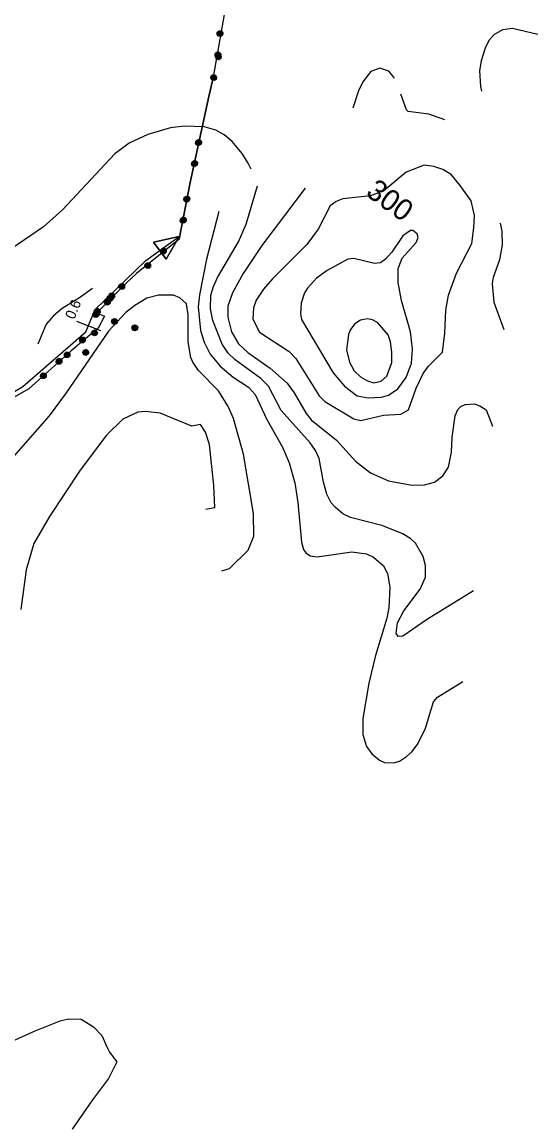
# Model space of a CAD drawing. Extents: x -645676 to -642474, y -1077513 to -1072613.
# Drawn here: x -643335 to -643033, y -1077131 to -1076485 of the extents above; entities that cross this region are included whole.
import ezdxf

# ---------------------------------------------------------------- set-up
doc = ezdxf.new("R2010")
doc.units = 0
for name, color, linetype in [('KULTURY_STAV', 7, 'Continuous'), ('OBVOD_PU', 7, 'Continuous'), ('PC_NAVRH', 7, 'Continuous'), ('PC_STAN_NAVRH', 7, 'Continuous'), ('SPRAV_HR_STAV', 7, 'Continuous'), ('VRSTEVNICE', 7, 'Continuous'), ('Vrstevnice_z_kladn_', 7, 'Continuous'), ('Vrstevnice_zd_razn_n____popis', 7, 'Continuous')]:
    doc.layers.add(name, color=color, linetype=linetype)

# ---------------------------------------------------------------- blocks, each defined once
blk = doc.blocks.new('$944')
blk.add_line((0, 1.5), (0, -1.5))
blk = doc.blocks.new('$920')
for points in [[(0, 0), (-2.8, 1.25), (-2.8, -1.25), (0, 0)], [(-2.8, 1.25), (0, 0), (-2.8, -1.25), (-2.8, 1.25)]]:
    blk.add_lwpolyline(points)
blk = doc.blocks.new('2$0620')
for points in [[(-1.07, 0.32), (-0.88, 0.13), (-0.88, -0.14), (-1.07, -0.33), (-1.34, -0.33), (-1.53, -0.14), (-1.53, 0.13), (-1.34, 0.32), (-1.07, 0.32), (-1.08, 0.28), (-1.32, 0.28), (-1.4, 0.2), (-1, 0.2), (-0.92, 0.12), (-1.48, 0.12), (-1.48, 0.04), (-0.92, 0.04), (-0.92, -0.04), (-1.48, -0.04), (-1.48, -0.12), (-0.92, -0.12), (-1, -0.2), (-1.4, -0.2), (-1.32, -0.28), (-1.08, -0.28)], [(1.43, 0.32), (1.62, 0.13), (1.62, -0.14), (1.43, -0.33), (1.16, -0.33), (0.97, -0.14), (0.97, 0.13), (1.16, 0.32), (1.43, 0.32), (1.4, 0.28), (1.16, 0.28), (1.08, 0.2), (1.48, 0.2), (1.56, 0.12), (1, 0.12), (1, 0.04), (1.56, 0.04), (1.56, -0.04), (1, -0.04), (1, -0.12), (1.56, -0.12), (1.48, -0.2), (1.08, -0.2), (1.16, -0.28), (1.4, -0.28)]]:
    blk.add_lwpolyline(points)

msp = doc.modelspace()

# ---------------------------------------------------------------- linework, layer by layer
at = {"layer": 'KULTURY_STAV'}
msp.add_lwpolyline([(-643217.03, -1076480.59), (-643223.78, -1076519.44), (-643226.07, -1076528.7), (-643236.93, -1076579.11), (-643243.33, -1076612.31), (-643268.3, -1076632.39), (-643274.14, -1076637.84), (-643275.51, -1076639.12), (-643291.65, -1076655.29), (-643287.15, -1076657.23), (-643290.93, -1076664.25), (-643306.74, -1076677.52), (-643331.48, -1076699.85), (-643347.3, -1076708.85)], dxfattribs=at)
at = {"layer": 'OBVOD_PU'}
msp.add_lwpolyline([(-643217.03, -1076480.59), (-643223.78, -1076519.44), (-643226.07, -1076528.7), (-643236.93, -1076579.11), (-643243.33, -1076612.31), (-643268.3, -1076632.39), (-643274.14, -1076637.84), (-643275.51, -1076639.12), (-643291.65, -1076655.29), (-643287.15, -1076657.23), (-643290.93, -1076664.25), (-643306.74, -1076677.52), (-643331.48, -1076699.85), (-643347.3, -1076708.85)], dxfattribs=at)
at = {"layer": 'PC_NAVRH'}
msp.add_lwpolyline([(-643797.12, -1076951.31), (-643789.53, -1076927.82), (-643783.02, -1076908.06), (-643774.79, -1076905.34), (-643762.9, -1076905.19), (-643748.59, -1076909.49), (-643740.43, -1076907.63), (-643712.08, -1076895.74), (-643647.09, -1076856.49), (-643620.93, -1076839.88), (-643580.45, -1076819.48), (-643516.12, -1076783.47), (-643467.4, -1076763.65), (-643449.91, -1076757.58), (-643363.17, -1076715.2), (-643334.98, -1076698.56), (-643297.97, -1076666.45), (-643292.62, -1076653.44), (-643262.84, -1076624.65), (-643243.46, -1076610.62)], dxfattribs=at)
at = {"layer": 'SPRAV_HR_STAV'}
for p, q in [((-643217.03, -1076480.59), (-643223.78, -1076519.44)), ((-643226.07, -1076528.7), (-643223.78, -1076519.44)), ((-643236.93, -1076579.11), (-643226.07, -1076528.7)), ((-643243.33, -1076612.31), (-643236.93, -1076579.11)), ((-643243.33, -1076612.31), (-643268.3, -1076632.39)), ((-643274.14, -1076637.84), (-643275.51, -1076639.12)), ((-643268.3, -1076632.39), (-643274.14, -1076637.84)), ((-643275.51, -1076639.12), (-643291.65, -1076655.29)), ((-643291.65, -1076655.29), (-643287.15, -1076657.23)), ((-643287.15, -1076657.23), (-643290.93, -1076664.25)), ((-643290.93, -1076664.25), (-643306.74, -1076677.52)), ((-643331.48, -1076699.85), (-643306.74, -1076677.52)), ((-643331.48, -1076699.85), (-643347.3, -1076708.85))]:
    msp.add_line(p, q, dxfattribs=at)
at = {"layer": 'VRSTEVNICE'}
for points in [[(-643033.11, -1076492.36), (-643048.05, -1076488.82), (-643053.85, -1076489.7), (-643058.98, -1076492.52), (-643061.96, -1076495.93), (-643063.95, -1076500.32), (-643066.31, -1076507.83), (-643067.39, -1076513.49), (-643066.81, -1076522.75), (-643066.21, -1076525.46)], [(-643117.14, -1076518.12), (-643117.57, -1076517.37), (-643120.47, -1076513.89), (-643125.68, -1076512.15), (-643131.04, -1076514.03), (-643135.82, -1076520.12), (-643138.28, -1076525.33), (-643141.5, -1076535.56)], [(-643087.59, -1076542.38), (-643097.01, -1076539.09), (-643109.17, -1076537.35), (-643110.18, -1076536.48), (-643113.55, -1076527.29)], [(-643201.27, -1076571.25), (-643202.87, -1076567.76), (-643206.49, -1076561.97), (-643212.28, -1076555.02), (-643217.06, -1076551.11), (-643221.84, -1076548.36), (-643228.79, -1076546.33), (-643240.38, -1076546.04), (-643248.49, -1076547.05), (-643261.81, -1076550.82), (-643272.67, -1076556.03), (-643281.07, -1076562.26), (-643311.78, -1076594.99), (-643322.93, -1076604.98), (-643341.46, -1076617.73)], [(-643070.87, -1076818.1), (-643097.87, -1076834.81), (-643112.36, -1076844.81), (-643114.96, -1076844.95), (-643116.27, -1076843.07), (-643115.4, -1076836.84), (-643111.65, -1076829.91), (-643102.22, -1076817.15), (-643099.03, -1076810.19), (-643099.03, -1076803.24), (-643100.34, -1076798.03), (-643104.97, -1076790.21), (-643107.58, -1076787.75), (-643112.36, -1076784.71), (-643124.52, -1076779.93), (-643143.06, -1076775.15), (-643147.4, -1076772.98), (-643152.04, -1076769.21), (-643154.21, -1076766.6), (-643156.82, -1076761.53), (-643158.84, -1076754.58), (-643161.31, -1076740.68), (-643163.48, -1076736.05), (-643166.66, -1076731.41), (-643183.61, -1076712.58), (-643190.99, -1076698.39), (-643195.48, -1076693.76), (-643210.55, -1076682.9), (-643214.74, -1076678.99), (-643218.22, -1076673.77), (-643223.72, -1076659.87), (-643225.03, -1076652.92), (-643224.74, -1076645.1), (-643223.29, -1076639.88), (-643220.83, -1076634.67), (-643208.66, -1076613.82), (-643204.17, -1076603.39), (-643197.54, -1076581.05)], [(-643169.55, -1076582.27), (-643194.9, -1076615.99), (-643205.91, -1076632.35), (-643212.14, -1076643.65), (-643214.89, -1076651.47), (-643214.89, -1076657.84), (-643212.72, -1076666.53), (-643208.52, -1076673.48), (-643203.16, -1076678.55), (-643189.98, -1076687.82), (-643179.99, -1076696.51), (-643175.93, -1076702.3), (-643168.98, -1076714.32), (-643165.94, -1076717.94), (-643151.17, -1076729.96), (-643140.02, -1076742.27), (-643131.18, -1076749.08), (-643120.76, -1076753.71), (-643106.85, -1076756.32), (-643099.61, -1076756.03), (-643093.67, -1076754.44), (-643088.9, -1076750.82), (-643085.56, -1076745.75), (-643083.68, -1076736.92), (-643083.39, -1076728.23), (-643081.65, -1076715.77), (-643080.06, -1076712), (-643078.32, -1076710.27), (-643075.72, -1076708.96), (-643070.36, -1076708.67), (-643067.2, -1076709.89), (-643063.41, -1076712.15), (-643059.7, -1076721.69)], [(-643220.18, -1076595.97), (-643227.43, -1076623.92), (-643231.54, -1076644.81), (-643232.27, -1076651.76), (-643230.82, -1076665.66), (-643228.65, -1076672.61), (-643225.17, -1076679.56), (-643219.38, -1076686.66), (-643211.7, -1076693.03), (-643202.73, -1076698.83), (-643198.81, -1076703.17), (-643192.01, -1076717.8), (-643182.74, -1076734.02), (-643178.83, -1076743.29), (-643175.5, -1076754.87), (-643173.76, -1076766.46), (-643171.73, -1076789.63), (-643170.57, -1076793.97), (-643169.13, -1076796), (-643166.66, -1076797.74), (-643162.46, -1076798.32), (-643142.19, -1076795.42), (-643133.5, -1076796.58), (-643129.45, -1076798.46), (-643123.65, -1076803.53), (-643121.34, -1076808.02), (-643119.89, -1076815.99), (-643120.47, -1076828.15), (-643121.63, -1076834.23), (-643128.29, -1076855.96), (-643132.2, -1076872.18), (-643135.82, -1076893.03), (-643135.67, -1076902.3), (-643133.5, -1076909.25), (-643130.46, -1076913.6), (-643125.97, -1076917.36), (-643123.07, -1076918.67), (-643117.57, -1076918.81), (-643114.24, -1076917.94), (-643110.16, -1076915.16), (-643106.85, -1076912.29), (-643103.52, -1076907.8), (-643099.03, -1076898.53), (-643094.25, -1076883.26), (-643091.96, -1076880.43), (-643077.04, -1076871.27)], [(-643055.3, -1076602.75), (-643054.28, -1076607.44), (-643054.14, -1076615.55), (-643055.59, -1076624.24), (-643059.35, -1076634.67), (-643059.93, -1076638.15), (-643059.06, -1076649.15), (-643053.14, -1076665.11)], [(-643294.21, -1076641.14), (-643301.78, -1076646.55), (-643311.92, -1076652.77), (-643316.99, -1076657.12), (-643321.33, -1076662.04), (-643326.26, -1076673.72)], [(-643218.34, -1076806.51), (-643213.8, -1076805.14), (-643202.87, -1076794.26), (-643199.68, -1076786.15), (-643199.83, -1076772.83), (-643205.62, -1076738.07), (-643211.56, -1076717.22), (-643214.6, -1076710.27), (-643220.25, -1076701), (-643231.98, -1076689.12), (-643235.31, -1076684.34), (-643236.47, -1076681.59), (-643238.06, -1076672.32), (-643238.06, -1076656.39), (-643239.08, -1076650.02), (-643242.99, -1076646.55), (-643246.75, -1076645.1), (-643255.44, -1076644.95), (-643262.39, -1076646.84), (-643269.34, -1076651.03), (-643274.56, -1076655.09), (-643284.69, -1076666.1), (-643309.6, -1076702.16), (-643319.6, -1076715.63), (-643340.45, -1076739.52)], [(-643227.79, -1076770.37), (-643222.44, -1076769.35), (-643223.08, -1076756.4), (-643225.53, -1076732.56), (-643228, -1076725.21), (-643230.88, -1076720.71), (-643236.03, -1076721.73), (-643254.57, -1076714.03), (-643263.26, -1076713.16), (-643267.61, -1076713.6), (-643276.29, -1076717.65), (-643286.14, -1076727.21), (-643301.78, -1076748.06), (-643319.45, -1076774.57), (-643328.57, -1076790.5), (-643333.06, -1076805.85), (-643336.11, -1076829.02)], [(-643399.1, -1077135.46), (-643395.63, -1077111.13), (-643392.59, -1077101.86), (-643385.49, -1077096.65), (-643365.79, -1077091.44), (-643351.02, -1077086.22), (-643327.85, -1077075.8), (-643313.08, -1077070), (-643308.16, -1077068.85), (-643300.77, -1077068.99), (-643293.67, -1077073.48), (-643288.6, -1077078.55), (-643285.83, -1077085.22), (-643284.19, -1077088.28), (-643279.86, -1077094.01), (-643284.8, -1077103.82), (-643294.07, -1077116.28), (-643306, -1077133.45)]]:
    msp.add_lwpolyline(points, dxfattribs=at)
for points in [[(-643072.34, -1076589.86), (-643078.77, -1076580.84), (-643083.97, -1076574.28), (-643088.9, -1076571.38), (-643094.11, -1076569.65), (-643099.76, -1076568.78), (-643110.33, -1076572.98), (-643123.51, -1076583.98), (-643131.18, -1076586.74), (-643147.4, -1076588.62), (-643151.46, -1076590.07), (-643154.79, -1076592.67), (-643161.89, -1076606.43), (-643168.55, -1076615.26), (-643188.68, -1076635.39), (-643193.89, -1076641.48), (-643198.24, -1076647.99), (-643199.83, -1076652.48), (-643200.26, -1076659), (-643196.21, -1076666.68), (-643178.83, -1076677.97), (-643174.92, -1076682.17), (-643161.31, -1076703.9), (-643157.98, -1076707.37), (-643141.03, -1076717.51), (-643136.98, -1076718.38), (-643123.65, -1076715.34), (-643113.51, -1076714.76), (-643109.03, -1076712.15), (-643104.54, -1076699.55), (-643100.34, -1076690.86), (-643097.29, -1076686.52), (-643089.12, -1076678.37), (-643087.62, -1076667.21), (-643087.01, -1076653.79), (-643085.56, -1076645.1), (-643080.93, -1076632.06), (-643071.95, -1076614.69), (-643070.74, -1076605.57), (-643070.32, -1076598.26)], [(-643114.96, -1076637.57), (-643115.11, -1076629.46), (-643112.65, -1076623.38), (-643104.39, -1076614.11), (-643103.38, -1076611.21), (-643103.96, -1076609.18), (-643106.42, -1076607.15), (-643107.87, -1076607.15), (-643112.21, -1076610.2), (-643118.73, -1076619.75), (-643122.49, -1076623.95), (-643125.39, -1076625.98), (-643128.87, -1076626.42), (-643141.03, -1076623.52), (-643144.51, -1076623.95), (-643156.67, -1076630.62), (-643162.9, -1076635.11), (-643168.26, -1076640.9), (-643170, -1076643.65), (-643171.88, -1076649.73), (-643172.17, -1076655.81), (-643171.59, -1076659.29), (-643153.05, -1076690.57), (-643146.39, -1076698.25), (-643139.15, -1076703.9), (-643132.63, -1076705.2), (-643124.81, -1076704.76), (-643120.76, -1076703.61), (-643115.25, -1076699.84), (-643110.33, -1076693.18), (-643107.14, -1076684.78), (-643106.56, -1076676.67), (-643107.72, -1076666.53), (-643113.06, -1076648.07)], [(-643127.2, -1076660.96), (-643130.02, -1076659.44), (-643132.92, -1076658.86), (-643137.01, -1076659.6), (-643140.35, -1076661.8), (-643142.91, -1076665.08), (-643144.07, -1076668.12), (-643145.38, -1076676.96), (-643143.64, -1076684.2), (-643140.74, -1076689.41), (-643137.12, -1076692.89), (-643132.92, -1076695.21), (-643129.27, -1076696.39), (-643125.06, -1076695.34), (-643121.63, -1076692.45), (-643118.73, -1076684.49), (-643118.73, -1076678.41), (-643119.6, -1076672.32), (-643120.9, -1076668.27)]]:
    msp.add_lwpolyline(points, close=True, dxfattribs=at)
at = {"layer": 'Vrstevnice_z_kladn_'}
msp.add_line((-643059.7, -1076721.7), (-643059.7, -1076721.69), dxfattribs=at)

# ---------------------------------------------------------------- block references
at = {"layer": 'PC_STAN_NAVRH', "xscale": 5, "yscale": 5}
for name, p, rotation in [('$920', (-643243.46, -1076610.62), 36.539795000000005), ('$944', (-643296.55, -1076663), 68.841485)]:
    msp.add_blockref(name, p, dxfattribs=dict(at, rotation=rotation))
at = {"layer": 'SPRAV_HR_STAV'}
for p, xscale, yscale, rotation in [((-643220.03, -1076497.83), 5, 5.000000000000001, -95.31612000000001), ((-643221.87, -1076511.71), 5, 4.999999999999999, 77.437793), ((-643233.24, -1076562), 5.000000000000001, 4.999999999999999, 79.200988), ((-643240.02, -1076595.13), 4.999999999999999, 4.999999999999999, 80.469232), ((-643256.97, -1076623.28), 5.000000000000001, 4.999999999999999, -137.37610400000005), ((-643281.09, -1076644.33), 5, 5, -133.085976), ((-643286.93, -1076649.79), 5, 5, -133.052105), ((-643287.87, -1076651.51), 5, 5, -131.01887700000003), ((-643275.58, -1076662.22), 5, 4.999999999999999, -17.445247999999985), ((-643304.33, -1076675.5), 5, 5, -136.15198100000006), ((-643295.45, -1076672.64), 5.000000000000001, 4.999999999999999, -114.082304), ((-643318.49, -1076688.12), 5, 4.999999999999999, 42.803239)]:
    msp.add_blockref('2$0620', p, dxfattribs=dict(at, xscale=xscale, yscale=yscale, rotation=rotation))

# ---------------------------------------------------------------- texts
at = {"layer": 'PC_STAN_NAVRH'}
msp.add_text('0.6', height=6, rotation=67.666, dxfattribs=at).set_placement((-643304.88, -1076659.59))
at = {"layer": 'Vrstevnice_zd_razn_n____popis'}
msp.add_text('300', height=12.5, rotation=324.018, dxfattribs=at).set_placement((-643134.67, -1076586.2))

doc.saveas('drawing.dxf')
